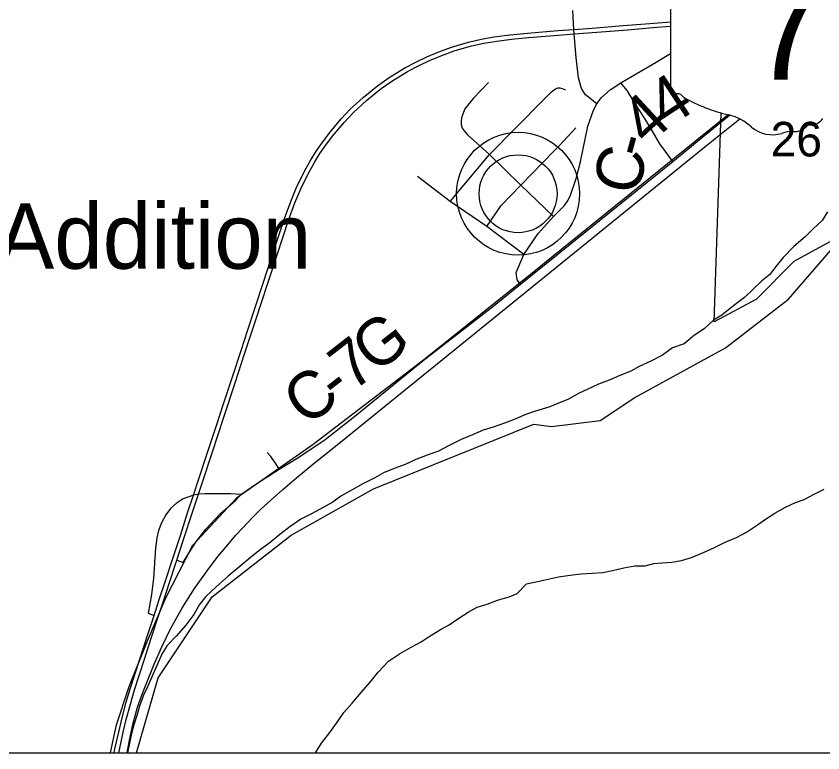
# Model space of a CAD drawing. Extents: x 2.1 to 8.9, y 14.1 to 20.9.
# Drawn here: x 6.556 to 7.533, y 14.1 to 14.992 of the extents above; entities that cross this region are included whole.
import ezdxf

# ---------------------------------------------------------------- set-up
doc = ezdxf.new("R2010")
doc.units = 0
for name, color, linetype in [('Default', 7, 'Continuous'), ('GM_X_City_Street', 7, 'Continuous'), ('GM_X_County_Road', 7, 'Continuous'), ('GM_X_County_Road_Text', 7, 'Continuous'), ('GM_X_Interchange_Ramps', 7, 'Continuous'), ('GM_X_Major_River', 7, 'Continuous'), ('GM_X_Minor_River', 7, 'Continuous'), ('GM_X_Rail_Line_Text', 7, 'Continuous'), ('GM_X_State_Location', 7, 'Continuous'), ('GM_X_State_Route', 7, 'Continuous'), ('GM_X_State_Shield', 7, 'Continuous'), ('GM_X_Township_Text', 7, 'Continuous'), ('GM_X_Unincorporated', 7, 'Continuous'), ('SC_Shading1', 7, 'Continuous'), ('SH_Cut_Line', 7, 'Continuous'), ('SH_Data', 7, 'Continuous')]:
    doc.layers.add(name, color=color, linetype=linetype)

msp = doc.modelspace()

# ---------------------------------------------------------------- linework, layer by layer
at = {"layer": 'Default'}
for p, q in [((7.49082, 14.64909), (7.58235, 14.75542)), ((7.41471, 14.59015), (7.49082, 14.64909)), ((7.30502, 14.53008), (7.41471, 14.59015)), ((7.26298, 14.50243), (7.30502, 14.53008)), ((6.98847, 14.41957), (7.18239, 14.49774)), ((7.18239, 14.49774), (7.20414, 14.49508)), ((7.20414, 14.49508), (7.26298, 14.50243)), ((6.88889, 14.36327), (6.98847, 14.41957)), ((6.79317, 14.28882), (6.88889, 14.36327)), ((6.72773, 14.19078), (6.79317, 14.28882)), ((6.70166, 14.1), (6.72773, 14.19078)), ((2.1, 14.1), (6.70166, 14.1))]:
    msp.add_line(p, q, dxfattribs=at)
at = {"layer": 'GM_X_City_Street'}
for p, q in [((7.23118, 14.97563), (7.22991, 14.99857)), ((7.23148, 14.9702), (7.23118, 14.97563)), ((7.23374, 14.94158), (7.23148, 14.9702)), ((7.23673, 14.91696), (7.23374, 14.94158)), ((7.24038, 14.90419), (7.23673, 14.91696)), ((7.1275, 14.91151), (7.10922, 14.89218)), ((7.29557, 14.90178), (7.28799, 14.91083)), ((7.19379, 14.88996), (7.20397, 14.90025)), ((7.20397, 14.90025), (7.20895, 14.90392)), ((7.20895, 14.90392), (7.21146, 14.90482)), ((7.21146, 14.90482), (7.21419, 14.90497)), ((7.21419, 14.90497), (7.21701, 14.90415)), ((7.21701, 14.90415), (7.22074, 14.90235)), ((7.24512, 14.89652), (7.24038, 14.90419)), ((7.2588, 14.88565), (7.24512, 14.89652)), ((7.30384, 14.8885), (7.29557, 14.90178)), ((7.10922, 14.89218), (7.09904, 14.87939)), ((7.1288, 14.82429), (7.19379, 14.88996)), ((7.31802, 14.86564), (7.30384, 14.8885)), ((7.09904, 14.87939), (7.09539, 14.86973)), ((7.09539, 14.86973), (7.09439, 14.86541)), ((7.09439, 14.86541), (7.09456, 14.86155)), ((7.09456, 14.86155), (7.09461, 14.86059)), ((7.09461, 14.86059), (7.09593, 14.85618)), ((7.32608, 14.85243), (7.31802, 14.86564)), ((7.09593, 14.85618), (7.09814, 14.85272)), ((7.09814, 14.85272), (7.10208, 14.8481)), ((7.10208, 14.8481), (7.1288, 14.82429)), ((7.21358, 14.83533), (7.23325, 14.85639)), ((7.33525, 14.83721), (7.32608, 14.85243)), ((7.34206, 14.82769), (7.33525, 14.83721)), ((7.16702, 14.7873), (7.20702, 14.82856)), ((7.20702, 14.82856), (7.21358, 14.83533)), ((7.35075, 14.81566), (7.34206, 14.82769)), ((7.08124, 14.76749), (7.1288, 14.82429)), ((7.1288, 14.82429), (7.16702, 14.7873)), ((7.08124, 14.76749), (7.04162, 14.79769)), ((7.14293, 14.76244), (7.16702, 14.7873)), ((7.16702, 14.7873), (7.20645, 14.74914)), ((7.12556, 14.737), (7.08124, 14.76749)), ((7.12556, 14.737), (7.14293, 14.76244)), ((7.17033, 14.70324), (7.12556, 14.737)), ((6.86399, 14.45874), (6.85988, 14.46352)), ((6.87066, 14.44942), (6.86399, 14.45874)), ((6.87441, 14.44317), (6.87066, 14.44942))]:
    msp.add_line(p, q, dxfattribs=at)
at = {"layer": 'GM_X_County_Road'}
msp.add_line((7.34804, 15.10094), (7.34804, 14.90081), dxfattribs=at)
for centre, radius, start, end in [((7.35109, 14.90038), 0.00308, 171.95839, 258.30661), ((7.35156, 14.92085), 0.02352, 267.33899, 280.60386), ((7.35637, 14.88927), 0.00848, 29.74838, 93.27175), ((7.46343, 15.06907), 0.20192, 240.41292, 257.1985), ((7.40323, 14.81091), 0.06318, 47.18416, 75.83597), ((7.51441, 14.88142), 0.0226, 282.87319, 323.27711), ((7.47156, 14.88828), 0.04009, 230.70037, 286.29184), ((7.49765, 14.87329), 0.02136, 268.77702, 315.54927), ((7.51697, 14.85391), 0.00601, 65.75173, 132.64842), ((7.49472, 14.81909), 0.03294, 85.69512, 111.20995)]:
    msp.add_arc(centre, radius, start, end, dxfattribs=at)
at = {"layer": 'GM_X_Interchange_Ramps'}
for p, q in [((7.40091, 14.62176), (7.40946, 14.87449)), ((7.54526, 14.72097), (7.49751, 14.6947)), ((7.49751, 14.6947), (7.45214, 14.64934)), ((7.45214, 14.64934), (7.40091, 14.62176))]:
    msp.add_line(p, q, dxfattribs=at)
at = {"layer": 'GM_X_Rail_Line_Text'}
for p, q in [((7.32306, 14.98284), (7.34804, 14.98491)), ((7.17491, 14.97125), (7.21182, 14.97417)), ((7.21182, 14.97417), (7.23118, 14.97563)), ((7.23118, 14.97563), (7.25332, 14.97736)), ((7.25332, 14.97736), (7.2908, 14.98033)), ((7.25897, 14.9725), (7.29623, 14.97535)), ((7.2908, 14.98033), (7.32306, 14.98284)), ((7.29623, 14.97535), (7.32653, 14.97779)), ((7.32653, 14.97779), (7.34804, 14.97948)), ((7.11874, 14.96373), (7.13466, 14.9665)), ((7.13466, 14.9665), (7.15371, 14.96921)), ((7.13776, 14.96159), (7.15562, 14.96403)), ((7.15371, 14.96921), (7.17491, 14.97125)), ((7.15562, 14.96403), (7.17592, 14.96597)), ((7.17592, 14.96597), (7.21254, 14.96889)), ((7.21254, 14.96889), (7.23148, 14.9702)), ((7.23148, 14.9702), (7.25897, 14.9725)), ((7.06769, 14.94864), (7.08303, 14.95433)), ((7.08303, 14.95433), (7.10334, 14.96029)), ((7.08612, 14.94957), (7.10711, 14.95569)), ((7.10334, 14.96029), (7.11874, 14.96373)), ((7.10711, 14.95569), (7.12212, 14.95888)), ((7.12212, 14.95888), (7.13776, 14.96159)), ((7.05296, 14.9426), (7.06769, 14.94864)), ((7.07104, 14.94429), (7.08612, 14.94957)), ((7.0262, 14.92904), (7.04031, 14.93648)), ((7.04031, 14.93648), (7.05296, 14.9426)), ((7.04365, 14.93212), (7.0563, 14.93824)), ((7.0563, 14.93824), (7.07104, 14.94429)), ((7.00743, 14.91751), (7.0262, 14.92904)), ((7.02954, 14.92469), (7.04365, 14.93212)), ((6.99334, 14.90745), (7.00743, 14.91751)), ((7.01078, 14.91315), (7.02954, 14.92469)), ((6.97575, 14.89315), (6.99334, 14.90745)), ((6.99763, 14.90417), (7.01078, 14.91315)), ((6.98054, 14.89021), (6.99763, 14.90417)), ((6.96038, 14.87893), (6.97575, 14.89315)), ((6.96372, 14.87458), (6.98054, 14.89021)), ((6.9494, 14.86753), (6.96038, 14.87893)), ((6.9355, 14.85085), (6.9494, 14.86753)), ((6.95274, 14.86318), (6.96372, 14.87458)), ((6.93884, 14.8465), (6.95274, 14.86318)), ((6.92625, 14.83834), (6.9355, 14.85085)), ((6.92028, 14.82979), (6.92625, 14.83834)), ((6.9296, 14.83399), (6.93884, 14.8465)), ((6.91274, 14.81782), (6.92028, 14.82979)), ((6.92362, 14.82544), (6.9296, 14.83399)), ((6.90501, 14.80419), (6.91274, 14.81782)), ((6.91743, 14.81529), (6.92362, 14.82544)), ((6.9093, 14.80083), (6.91743, 14.81529)), ((6.89499, 14.78363), (6.90501, 14.80419)), ((6.90032, 14.78257), (6.9093, 14.80083)), ((6.88914, 14.76948), (6.89499, 14.78363)), ((6.89325, 14.76559), (6.90032, 14.78257)), ((6.88126, 14.74818), (6.88914, 14.76948)), ((6.88567, 14.74481), (6.89325, 14.76559)), ((6.87124, 14.71879), (6.88126, 14.74818)), ((6.8717, 14.70262), (6.88567, 14.74481)), ((6.86408, 14.69707), (6.87124, 14.71879)), ((6.86009, 14.66739), (6.8717, 14.70262)), ((6.85484, 14.66841), (6.86408, 14.69707)), ((6.84524, 14.63923), (6.85484, 14.66841)), ((6.84619, 14.62527), (6.86009, 14.66739)), ((6.83589, 14.61083), (6.84524, 14.63923)), ((6.83229, 14.58308), (6.84619, 14.62527)), ((6.82848, 14.58833), (6.83589, 14.61083)), ((6.81694, 14.55273), (6.82848, 14.58833)), ((6.82089, 14.54805), (6.83229, 14.58308)), ((6.80713, 14.50621), (6.82089, 14.54805)), ((6.80723, 14.52354), (6.81694, 14.55273)), ((6.79778, 14.49494), (6.80723, 14.52354)), ((6.79344, 14.46437), (6.80713, 14.50621)), ((6.78828, 14.46607), (6.79778, 14.49494)), ((6.77669, 14.43052), (6.78828, 14.46607)), ((6.78176, 14.42864), (6.79344, 14.46437)), ((6.77044, 14.41177), (6.77669, 14.43052)), ((6.77666, 14.41304), (6.78176, 14.42864)), ((6.76385, 14.39173), (6.77044, 14.41177)), ((6.76979, 14.3925), (6.77666, 14.41304)), ((6.75461, 14.36322), (6.76385, 14.39173)), ((6.75819, 14.35719), (6.76979, 14.3925)), ((6.74532, 14.3353), (6.75461, 14.36322)), ((6.75028, 14.33325), (6.75819, 14.35719)), ((6.73611, 14.30688), (6.74532, 14.3353)), ((6.74107, 14.30484), (6.75028, 14.33325)), ((6.72909, 14.28547), (6.73611, 14.30688)), ((6.73405, 14.28343), (6.74107, 14.30484)), ((6.7227, 14.26639), (6.72909, 14.28547)), ((6.72757, 14.26452), (6.73405, 14.28343)), ((6.71449, 14.24092), (6.7227, 14.26639)), ((6.71981, 14.24003), (6.72757, 14.26452)), ((6.70504, 14.21215), (6.71449, 14.24092)), ((6.71064, 14.21213), (6.71981, 14.24003)), ((6.69334, 14.17608), (6.70504, 14.21215)), ((6.69903, 14.17627), (6.71064, 14.21213)), ((6.68911, 14.16115), (6.69334, 14.17608)), ((6.69408, 14.15909), (6.69903, 14.17627)), ((6.68422, 14.14234), (6.68911, 14.16115)), ((6.68909, 14.14047), (6.69408, 14.15909)), ((6.67993, 14.12502), (6.68422, 14.14234)), ((6.68548, 14.12491), (6.68909, 14.14047)), ((6.67544, 14.10503), (6.67993, 14.12502)), ((6.68089, 14.10378), (6.68548, 14.12491)), ((6.67452, 14.1), (6.67544, 14.10503)), ((6.68014, 14.1), (6.68089, 14.10378))]:
    msp.add_line(p, q, dxfattribs=at)
at = {"layer": 'GM_X_State_Location'}
for p, q in [((7.53832, 14.75484), (7.53169, 14.74448)), ((7.53169, 14.74448), (7.5209, 14.73441)), ((7.5209, 14.73441), (7.51123, 14.72474)), ((7.51123, 14.72474), (7.49745, 14.71272)), ((7.49745, 14.71272), (7.48444, 14.69958)), ((7.48444, 14.69958), (7.47555, 14.68879)), ((7.47555, 14.68879), (7.46816, 14.67916)), ((7.45808, 14.67101), (7.44804, 14.66133)), ((7.46816, 14.67916), (7.45808, 14.67101)), ((7.44804, 14.66133), (7.43763, 14.65127)), ((7.43763, 14.65127), (7.42455, 14.64154)), ((7.42455, 14.64154), (7.41, 14.62989)), ((7.40027, 14.62363), (7.38872, 14.61317)), ((7.41, 14.62989), (7.40027, 14.62363)), ((7.38872, 14.61317), (7.37712, 14.60574)), ((7.37712, 14.60574), (7.36444, 14.59526)), ((7.36444, 14.59526), (7.35052, 14.59007)), ((7.35052, 14.59007), (7.33818, 14.58148)), ((7.3243, 14.57401), (7.31002, 14.56767)), ((7.33818, 14.58148), (7.3243, 14.57401)), ((7.31002, 14.56767), (7.2999, 14.56217)), ((7.28674, 14.55661), (7.27397, 14.55106)), ((7.2999, 14.56217), (7.28674, 14.55661)), ((7.2608, 14.54626), (7.24728, 14.53993)), ((7.27397, 14.55106), (7.2608, 14.54626)), ((7.23752, 14.53519), (7.22439, 14.52811)), ((7.24728, 14.53993), (7.23752, 14.53519)), ((7.22439, 14.52811), (7.21161, 14.52294)), ((7.20183, 14.51896), (7.18344, 14.51321)), ((7.21161, 14.52294), (7.20183, 14.51896)), ((7.17178, 14.50922), (7.16014, 14.50408)), ((7.18344, 14.51321), (7.17178, 14.50922)), ((7.14698, 14.49892), (7.13344, 14.49414)), ((7.16014, 14.50408), (7.14698, 14.49892)), ((7.12139, 14.49051), (7.10824, 14.48498)), ((7.13344, 14.49414), (7.12139, 14.49051)), ((7.09472, 14.47943), (7.08009, 14.47197)), ((7.10824, 14.48498), (7.09472, 14.47943)), ((7.08009, 14.47197), (7.06733, 14.4653)), ((7.05342, 14.46013), (7.03989, 14.45496)), ((7.06733, 14.4653), (7.05342, 14.46013)), ((7.02674, 14.44905), (7.01471, 14.44466)), ((7.03989, 14.45496), (7.02674, 14.44905)), ((7.00155, 14.43951), (6.98994, 14.43286)), ((7.01471, 14.44466), (7.00155, 14.43951)), ((6.98994, 14.43286), (6.97568, 14.42578)), ((6.96256, 14.41835), (6.94907, 14.41053)), ((6.97568, 14.42578), (6.96256, 14.41835)), ((7.52181, 14.41314), (7.5342, 14.41907)), ((6.94907, 14.41053), (6.93936, 14.40353)), ((7.50981, 14.40646), (7.52181, 14.41314)), ((6.93936, 14.40353), (6.92661, 14.39649)), ((7.48725, 14.39731), (7.49927, 14.40285)), ((7.49927, 14.40285), (7.50981, 14.40646)), ((6.91424, 14.38982), (6.90036, 14.38275)), ((6.92661, 14.39649), (6.91424, 14.38982)), ((7.4644, 14.3836), (7.47451, 14.39024)), ((7.47451, 14.39024), (7.48725, 14.39731)), ((6.90036, 14.38275), (6.88727, 14.37343)), ((7.45356, 14.37581), (7.4644, 14.3836)), ((6.88727, 14.37343), (6.87494, 14.36411)), ((7.44009, 14.36721), (7.45356, 14.37581)), ((6.87494, 14.36411), (6.86338, 14.35443)), ((7.41418, 14.35496), (7.42809, 14.36053)), ((7.42809, 14.36053), (7.44009, 14.36721)), ((6.86338, 14.35443), (6.85142, 14.34588)), ((7.3879, 14.34232), (7.40142, 14.34864)), ((7.40142, 14.34864), (7.41418, 14.35496)), ((6.85142, 14.34588), (6.83947, 14.33657)), ((7.37361, 14.33636), (7.3879, 14.34232)), ((6.83947, 14.33657), (6.82642, 14.32534)), ((7.31735, 14.32619), (7.3279, 14.32904)), ((7.3279, 14.32904), (7.33774, 14.32999)), ((7.33774, 14.32999), (7.34947, 14.33059)), ((7.34947, 14.33059), (7.36156, 14.33271)), ((7.36156, 14.33271), (7.37361, 14.33636)), ((6.82642, 14.32534), (6.81262, 14.31372)), ((7.26596, 14.31838), (7.27766, 14.32088)), ((7.27766, 14.32088), (7.29163, 14.3238)), ((7.29163, 14.3238), (7.30484, 14.32633)), ((7.30484, 14.32633), (7.31735, 14.32619)), ((6.81262, 14.31372), (6.79808, 14.30096)), ((7.18687, 14.30746), (7.21263, 14.3132)), ((7.21263, 14.3132), (7.22662, 14.31498)), ((7.22662, 14.31498), (7.23985, 14.31675)), ((7.23985, 14.31675), (7.25348, 14.31739)), ((7.25348, 14.31739), (7.26596, 14.31838)), ((6.79808, 14.30096), (6.78541, 14.28936)), ((7.16229, 14.2929), (7.17382, 14.30448)), ((7.17382, 14.30448), (7.18687, 14.30746)), ((7.15252, 14.28894), (7.16229, 14.2929)), ((6.78541, 14.28936), (6.77764, 14.27936)), ((7.12619, 14.27975), (7.13859, 14.2849)), ((7.13859, 14.2849), (7.15252, 14.28894)), ((6.77764, 14.27936), (6.77104, 14.26749)), ((7.10289, 14.27025), (7.11414, 14.27613)), ((7.11414, 14.27613), (7.12619, 14.27975)), ((6.77104, 14.26749), (6.76105, 14.25443)), ((7.08007, 14.25506), (7.09055, 14.26207)), ((7.09055, 14.26207), (7.10289, 14.27025)), ((6.76105, 14.25443), (6.74954, 14.24133)), ((7.06957, 14.24919), (7.08007, 14.25506)), ((6.74954, 14.24133), (6.73877, 14.22977)), ((7.05572, 14.24061), (7.06957, 14.24919)), ((7.03399, 14.22809), (7.04599, 14.23437)), ((7.04599, 14.23437), (7.05572, 14.24061)), ((6.73877, 14.22977), (6.7325, 14.22018)), ((7.01975, 14.21988), (7.03399, 14.22809)), ((6.7325, 14.22018), (6.72157, 14.19572)), ((7.00666, 14.21093), (7.01975, 14.21988)), ((6.99402, 14.19782), (7.00666, 14.21093)), ((6.72157, 14.19572), (6.71502, 14.18082)), ((6.98439, 14.18551), (6.99402, 14.19782)), ((6.97363, 14.17319), (6.98439, 14.18551)), ((6.71502, 14.18082), (6.70991, 14.16973)), ((6.96251, 14.1601), (6.97363, 14.17319)), ((6.70991, 14.16973), (6.70522, 14.15637)), ((6.70522, 14.15637), (6.70237, 14.14646)), ((6.95248, 14.14893), (6.96251, 14.1601)), ((6.70237, 14.14646), (6.69842, 14.13388)), ((6.94547, 14.13857), (6.95248, 14.14893)), ((6.69842, 14.13388), (6.69557, 14.12359)), ((6.93549, 14.12475), (6.94547, 14.13857)), ((6.9255, 14.11168), (6.93549, 14.12475)), ((6.69557, 14.12359), (6.69279, 14.10951)), ((6.69279, 14.10951), (6.69073, 14.1)), ((6.91834, 14.1), (6.9255, 14.11168))]:
    msp.add_line(p, q, dxfattribs=at)
at = {"layer": 'GM_X_State_Route'}
for radius in [0.0744, 0.04716]:
    msp.add_circle((7.16352, 14.77671), radius, dxfattribs=at)
at = {"layer": 'GM_X_State_Shield'}
for p, q in [((7.33067, 14.93583), (7.34804, 14.94647)), ((7.30175, 14.91894), (7.33067, 14.93583)), ((7.28799, 14.91083), (7.30175, 14.91894)), ((7.27602, 14.90331), (7.28799, 14.91083)), ((7.26391, 14.89277), (7.27522, 14.9028)), ((7.27522, 14.9028), (7.27602, 14.90331)), ((7.2588, 14.88565), (7.26391, 14.89277)), ((7.24804, 14.85864), (7.25497, 14.8778)), ((7.25497, 14.8778), (7.2588, 14.88565)), ((7.38738, 14.84583), (7.41968, 14.87194)), ((7.23926, 14.81549), (7.24804, 14.85864)), ((7.35075, 14.81566), (7.38738, 14.84583)), ((7.16638, 14.66727), (7.35075, 14.81566)), ((7.23399, 14.79526), (7.23926, 14.81549)), ((7.22693, 14.77491), (7.23399, 14.79526)), ((7.21973, 14.76272), (7.22416, 14.76879)), ((7.22416, 14.76879), (7.22693, 14.77491)), ((7.20645, 14.74914), (7.21973, 14.76272)), ((7.18784, 14.72871), (7.20645, 14.74914)), ((7.17033, 14.70324), (7.18784, 14.72871)), ((7.16121, 14.68126), (7.17033, 14.70324)), ((7.1623, 14.67251), (7.16121, 14.68126)), ((7.16638, 14.66727), (7.1623, 14.67251)), ((7.13461, 14.64157), (7.16638, 14.66727)), ((7.04873, 14.57481), (7.13461, 14.64157)), ((7.00271, 14.53742), (7.04873, 14.57481)), ((6.96588, 14.50753), (7.00271, 14.53742)), ((6.93001, 14.47931), (6.96588, 14.50753)), ((6.89679, 14.45693), (6.93001, 14.47931)), ((6.87441, 14.44317), (6.89679, 14.45693)), ((6.84717, 14.42621), (6.87441, 14.44317)), ((6.82785, 14.41273), (6.84717, 14.42621))]:
    msp.add_line(p, q, dxfattribs=at)
at = {"layer": 'GM_X_Township_Text'}
msp.add_line((7.16352, 14.77671), (7.16352, 14.77671), dxfattribs=at)
at = {"layer": 'GM_X_Unincorporated'}
for p, q in [((6.75819, 14.40731), (6.7495, 14.40168)), ((6.77044, 14.41177), (6.75819, 14.40731)), ((6.77666, 14.41304), (6.77044, 14.41177)), ((6.78451, 14.41339), (6.77666, 14.41304)), ((6.81536, 14.41351), (6.78451, 14.41339)), ((6.82785, 14.41273), (6.81536, 14.41351)), ((6.82192, 14.40585), (6.82785, 14.41273)), ((6.7495, 14.40168), (6.74276, 14.39556)), ((6.80267, 14.38937), (6.82192, 14.40585)), ((6.73685, 14.38791), (6.73164, 14.37846)), ((6.74276, 14.39556), (6.73685, 14.38791)), ((6.78536, 14.37089), (6.80267, 14.38937)), ((6.73164, 14.37846), (6.72823, 14.36894)), ((6.72823, 14.36894), (6.72607, 14.36032)), ((6.77334, 14.35504), (6.78536, 14.37089)), ((6.72607, 14.36032), (6.72462, 14.34802)), ((6.76597, 14.34378), (6.77334, 14.35504)), ((6.72462, 14.34802), (6.72204, 14.31153)), ((6.75805, 14.33023), (6.76597, 14.34378)), ((6.75028, 14.33325), (6.75805, 14.33023)), ((6.72204, 14.31153), (6.71954, 14.29179)), ((6.71954, 14.29179), (6.71553, 14.26914)), ((6.71553, 14.26914), (6.7227, 14.26639))]:
    msp.add_line(p, q, dxfattribs=at)
at = {"layer": 'SC_Shading1'}
for p, q in [((7.41781, 14.87237), (7.19564, 14.69284)), ((7.38977, 14.83342), (7.43184, 14.86724)), ((7.17225, 14.65714), (7.38977, 14.83342)), ((7.19564, 14.69284), (7.17998, 14.68012)), ((7.17998, 14.68012), (7.04751, 14.57406)), ((6.95475, 14.48147), (7.17225, 14.65714)), ((7.04751, 14.57406), (6.91535, 14.47339)), ((6.91408, 14.44862), (6.95475, 14.48147)), ((6.91535, 14.47339), (6.82266, 14.40828)), ((6.89558, 14.43318), (6.91408, 14.44862)), ((6.87876, 14.41893), (6.89558, 14.43318)), ((6.86372, 14.40538), (6.87876, 14.41893)), ((6.82266, 14.40828), (6.76935, 14.35099)), ((6.85254, 14.39538), (6.86372, 14.40538)), ((6.84205, 14.3847), (6.85254, 14.39538)), ((6.83028, 14.37253), (6.84205, 14.3847)), ((6.82137, 14.36303), (6.83028, 14.37253)), ((6.81197, 14.35185), (6.82137, 14.36303)), ((6.76935, 14.35099), (6.73676, 14.28711)), ((6.8, 14.3377), (6.81197, 14.35185)), ((6.78694, 14.32048), (6.8, 14.3377)), ((6.7718, 14.29901), (6.78694, 14.32048)), ((6.75716, 14.27576), (6.7718, 14.29901)), ((6.73676, 14.28711), (6.71426, 14.23521)), ((6.74291, 14.25073), (6.75716, 14.27576)), ((6.73222, 14.22837), (6.74291, 14.25073)), ((6.71426, 14.23521), (6.69231, 14.17996)), ((6.72282, 14.20719), (6.73222, 14.22837)), ((6.70907, 14.17296), (6.72282, 14.20719)), ((6.69231, 14.17996), (6.6765, 14.13243)), ((6.70264, 14.15515), (6.70907, 14.17296)), ((6.69749, 14.13605), (6.70264, 14.15515)), ((6.69284, 14.11527), (6.69749, 14.13605)), ((6.6765, 14.13243), (6.6697, 14.1)), ((6.69008, 14.1), (6.69284, 14.11527))]:
    msp.add_line(p, q, dxfattribs=at)
at = {"layer": 'SH_Cut_Line'}
for p, q in [((7.49082, 14.64909), (7.58235, 14.75542)), ((7.41471, 14.59015), (7.49082, 14.64909)), ((7.30502, 14.53008), (7.41471, 14.59015)), ((7.26298, 14.50243), (7.30502, 14.53008)), ((6.98847, 14.41957), (7.18239, 14.49774)), ((7.18239, 14.49774), (7.20414, 14.49508)), ((7.20414, 14.49508), (7.26298, 14.50243)), ((6.88889, 14.36327), (6.98847, 14.41957)), ((6.79317, 14.28882), (6.88889, 14.36327)), ((6.72773, 14.19078), (6.79317, 14.28882)), ((6.70166, 14.1), (6.72773, 14.19078)), ((2.1, 14.1), (6.70166, 14.1))]:
    msp.add_line(p, q, dxfattribs=at)
at = {"layer": 'SH_Data'}
for p, q in [((2.1, 14.1), (8.9, 14.1)), ((2.1, 14.09996), (8.9, 14.09996))]:
    msp.add_line(p, q, dxfattribs=at)

# ---------------------------------------------------------------- texts
at = {"layer": 'GM_X_County_Road'}
msp.add_text('7', height=0.13184, dxfattribs=at).set_placement((7.4421, 14.91493))
at = {"layer": 'GM_X_County_Road_Text'}
msp.add_text('26', height=0.041856, rotation=0.00001, dxfattribs=at).set_placement((7.46921, 14.8219))
at = {"layer": 'GM_X_Major_River'}
msp.add_text('Pottery Addition', height=0.0789773, rotation=0.00001, dxfattribs=at).set_placement((6.16755, 14.68597))
at = {"layer": 'GM_X_Minor_River'}
for s, rotation, p in [('4', 33.3056, (7.34403, 14.85511)), ('4', 42.82565, (7.32053, 14.83304)), ('-', 74.74371, (7.31872, 14.8178)), ('C', 77.00876, (7.30845, 14.77324)), ('G', 37.79702, (6.99046, 14.55761)), ('7', 37.79395, (6.96302, 14.53633)), ('C', 36.86754, (6.90689, 14.49377)), ('-', 37.77707, (6.94473, 14.52216))]:
    msp.add_text(s, height=0.05682, rotation=rotation, dxfattribs=at).set_placement(p)

doc.saveas('drawing.dxf')
